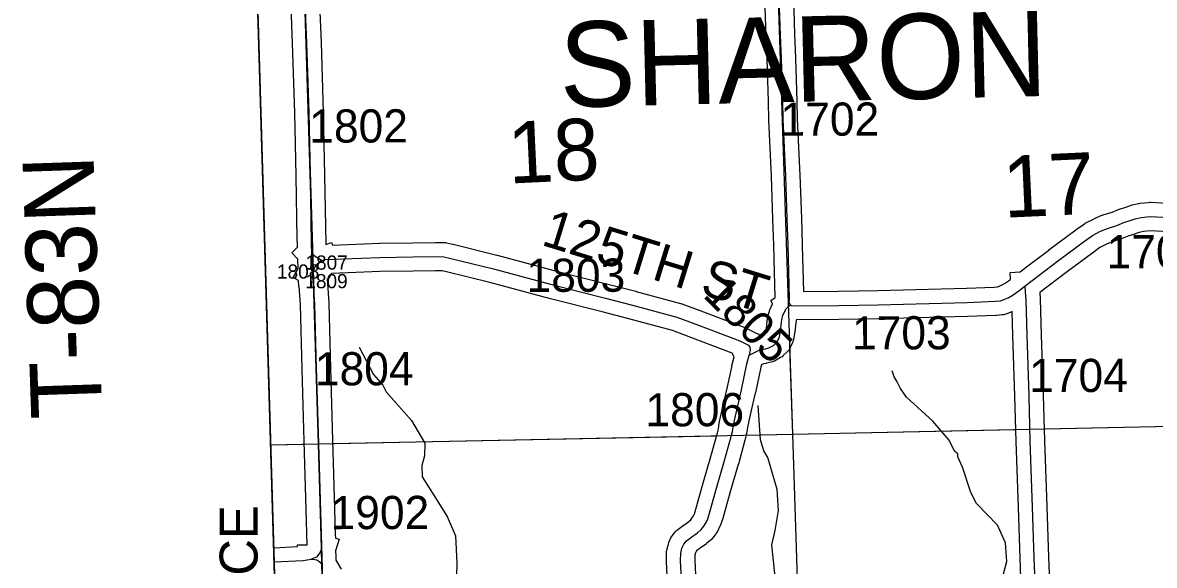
# Model space of a CAD drawing. Extents: x 128.7 to 185.5, y -21.4 to 12.6.
# Drawn here: x 133.254 to 135.642, y 1.081 to 2.226 of the extents above; entities that cross this region are included whole.
import ezdxf

# ---------------------------------------------------------------- set-up
doc = ezdxf.new("R2010")
doc.units = 0
for name, color, linetype in [('tdCoClipBndry', 7, 'Continuous'), ('tdCoCoBndry', 7, 'Continuous'), ('tdCoHydroRiver', 7, 'Continuous'), ('tdCoPipeTxt', 7, 'Continuous'), ('tdCoSecRdNmbr', 7, 'Continuous'), ('tdCoSecRdTxt', 7, 'Continuous'), ('tdCoSecRteBand', 7, 'Continuous'), ('tdCoSecRteCL', 7, 'Continuous'), ('tdCoSectLine', 7, 'Continuous'), ('tdCoSectLinePart', 7, 'Continuous'), ('tdCoSectNmbr', 7, 'Continuous'), ('tdCoSurfGravel', 7, 'Continuous'), ('tdCoTwpBndryShd', 7, 'Continuous'), ('tdCoTwpNameTxt', 7, 'Continuous'), ('tdCoTwpRngTxt', 7, 'Continuous')]:
    doc.layers.add(name, color=color, linetype=linetype)

msp = doc.modelspace()

# ---------------------------------------------------------------- linework, layer by layer
at = {"layer": 'tdCoClipBndry'}
msp.add_lwpolyline([(134.0612, -7.7025), (133.8962, -2.6807), (133.6887, 4.3446), (133.6938, 4.3792), (133.7053, 4.4028), (133.7226, 4.4226), (133.7445, 4.4372), (133.7868, 4.4475), (134.771, 4.4649), (135.7559, 4.4935), (136.7866, 4.5129), (139.7725, 4.5879), (146.7594, 4.806), (147.7608, 4.8492), (149.7557, 4.9088), (150.75, 4.946), (153.7332, 5.0633)], dxfattribs=at)
at = {"layer": 'tdCoCoBndry'}
for p, q in [((133.8784, 1.3376), (133.8476, 2.341)), ((133.8476, 2.341), (133.8784, 1.3376)), ((133.9071, 0.3357), (133.8784, 1.3376)), ((133.8784, 1.3376), (133.9071, 0.3357))]:
    msp.add_line(p, q, dxfattribs=at)
msp.add_lwpolyline([(133.7861, 4.4473), (133.7445, 4.4372), (133.7226, 4.4226), (133.7053, 4.4028), (133.6938, 4.3792), (133.6887, 4.3446), (133.8665, -1.6741), (133.9676, -1.6731), (133.9395, -0.6703), (133.9071, 0.3357), (133.8784, 1.3376), (133.8476, 2.341), (133.8192, 3.3421), (133.789, 4.3475), (133.7889, 4.3556)], close=True, dxfattribs=at)
for points in [[(134.1615, -7.6994), (134.1297, -6.7029), (134.1294, -6.6932), (134.095, -5.6895), (134.0611, -4.6883), (134.0307, -3.6816), (133.9965, -2.6778), (133.9676, -1.6731), (133.9395, -0.6703), (133.9071, 0.3357), (133.8784, 1.3376), (133.8476, 2.341), (133.8192, 3.3421), (133.789, 4.3475), (134.7737, 4.365), (135.7592, 4.3936), (135.7859, 4.3937), (136.7735, 4.4131), (136.7891, 4.4129), (137.7728, 4.4375)], [(133.7886, 4.3475), (133.8188, 3.3421), (133.8473, 2.341), (133.878, 1.3376), (133.9067, 0.3357), (133.9391, -0.6703), (133.9673, -1.6731), (133.9961, -2.6778), (134.0303, -3.6816), (134.0608, -4.6883), (134.0947, -5.6895), (134.129, -6.6932), (134.1293, -6.7029), (134.1612, -7.6994), (134.1875, -8.683), (134.2186, -9.7062), (134.2417, -10.7094), (134.275, -11.7191), (134.2997, -12.7212), (134.329, -13.723)]]:
    msp.add_lwpolyline(points, dxfattribs=at)
at = {"layer": 'tdCoHydroRiver'}
for points in [[(133.9644, 1.5416), (133.9945, 1.4841), (134.0141, 1.461), (134.0209, 1.447), (134.0747, 1.3871), (134.103, 1.339), (134.1022, 1.3122), (134.0965, 1.2915), (134.0972, 1.2679), (134.1237, 1.226), (134.1502, 1.1842), (134.1671, 1.1437), (134.1705, 1.0854), (134.1681, 1.0049)], [(135.3192, 1.0476), (135.3305, 1.089), (135.3277, 1.1283), (135.3107, 1.1657), (135.2667, 1.2116), (135.2549, 1.2349), (135.2375, 1.288), (135.2273, 1.3098), (135.2271, 1.3161), (135.2206, 1.3222), (135.2089, 1.3455), (135.1745, 1.3855), (135.1193, 1.4358), (135.1061, 1.4543), (135.0993, 1.4683), (135.0927, 1.4792), (135.0891, 1.4917)], [(134.8441, 1.0361), (134.8352, 1.1242), (134.8422, 1.1543), (134.8488, 1.1971), (134.8459, 1.2412), (134.8265, 1.3085), (134.8182, 1.3225), (134.8112, 1.3459), (134.8059, 1.4183)]]:
    msp.add_lwpolyline(points, dxfattribs=at)
at = {"layer": 'tdCoSecRteBand'}
for points in [[(133.784, 1.1183), (133.8341, 1.1209), (133.8342, 1.1247), (133.8542, 1.1241), (133.8524, 1.1988), (133.8482, 1.3435), (133.8482, 1.3435), (133.8482, 1.3435), (133.844, 1.4949), (133.844, 1.4949), (133.844, 1.4949), (133.8403, 1.6316), (133.8375, 1.6695), (133.8367, 1.6695), (133.8363, 1.6822), (133.8251, 1.6883), (133.8355, 1.7075), (133.8349, 1.7276), (133.8221, 1.7406), (133.8341, 1.7524), (133.8339, 1.7589), (133.8339, 1.7591), (133.8339, 1.7591), (133.8336, 1.7692), (133.8337, 1.7692), (133.8312, 1.9033), (133.8284, 2.036), (133.8238, 2.1824), (133.819, 2.3006)], [(133.8785, 2.3156), (133.8837, 2.1847), (133.8837, 2.1846), (133.8837, 2.1845), (133.8884, 2.0377), (133.8884, 2.0376), (133.8884, 2.0374), (133.8911, 1.9045), (133.8911, 1.9045), (133.8911, 1.9044), (133.8939, 1.7606), (133.8939, 1.7585), (133.906, 1.7622), (133.9076, 1.757), (134.0068, 1.7609), (134.0072, 1.761), (134.0076, 1.761), (134.0771, 1.762), (134.1252, 1.7627), (134.1259, 1.7627), (134.1265, 1.7627), (134.1435, 1.7622), (134.1461, 1.7621), (134.1486, 1.7616), (134.1609, 1.7592), (134.1615, 1.759), (134.1622, 1.7589), (134.2549, 1.7359), (134.2552, 1.7359), (134.2556, 1.7358), (134.383, 1.7013), (134.4915, 1.674), (134.4916, 1.674), (134.4917, 1.674), (134.5482, 1.6594), (134.5484, 1.6594), (134.5485, 1.6593), (134.6423, 1.6339), (134.6436, 1.6335), (134.645, 1.633), (134.6849, 1.618), (134.6849, 1.618), (134.685, 1.618), (134.7782, 1.5827), (134.7795, 1.5822), (134.7807, 1.5816), (134.7989, 1.5727), (134.8065, 1.5691), (134.8086, 1.5657)], [(134.8086, 1.5657), (134.8096, 1.5659), (134.8173, 1.568), (134.8199, 1.5695), (134.8219, 1.5714), (134.822, 1.5718), (134.8235, 1.5801), (134.8258, 1.6029), (134.8262, 1.6061), (134.8271, 1.6091), (134.8298, 1.6175), (134.8303, 1.6188), (134.8308, 1.62), (134.8365, 1.6333), (134.8366, 1.6337), (134.8326, 1.6399), (134.842, 1.6461), (134.8397, 1.7283), (134.8397, 1.7285), (134.8397, 1.7287), (134.8392, 1.7565), (134.8372, 1.812), (134.8372, 1.812), (134.8372, 1.812), (134.8342, 1.9021), (134.8286, 2.0205), (134.8286, 2.0209), (134.8286, 2.0213), (134.8278, 2.0594), (134.8251, 2.1497), (134.8229, 2.1986), (134.8229, 2.1988), (134.8229, 2.199), (134.8204, 2.2768)], [(134.8804, 2.2791), (134.8829, 2.2011), (134.8851, 2.1522), (134.8851, 2.152), (134.8851, 2.1518), (134.8878, 2.061), (134.8878, 2.0609), (134.8878, 2.0607), (134.8885, 2.0229), (134.8942, 1.9047), (134.8942, 1.9045), (134.8942, 1.9043), (134.8972, 1.814), (134.8991, 1.7584), (134.8991, 1.7581), (134.8992, 1.7578), (134.8996, 1.7299), (134.9017, 1.659)], [(134.9017, 1.659), (134.9756, 1.6598), (135.0584, 1.661), (135.2459, 1.6659), (135.3042, 1.6684), (135.3109, 1.6689), (135.3157, 1.6708), (135.3207, 1.6728), (135.3258, 1.6756), (135.3381, 1.6845), (135.3388, 1.685), (135.338, 1.699), (135.3587, 1.7003), (135.3753, 1.7129), (135.4194, 1.7466), (135.4195, 1.7467), (135.4196, 1.7468), (135.4763, 1.7892), (135.4767, 1.7895), (135.4771, 1.7898), (135.4944, 1.8018), (135.496, 1.803), (135.4977, 1.8039), (135.5147, 1.8127), (135.5159, 1.8134), (135.5171, 1.8139), (135.5314, 1.8198), (135.5326, 1.8203), (135.5337, 1.8206), (135.5527, 1.8267), (135.5665, 1.8322), (135.5674, 1.8326), (135.5683, 1.8329), (135.5815, 1.8372), (135.5915, 1.8408), (135.5934, 1.8415), (135.5954, 1.8419), (135.6082, 1.8446), (135.6097, 1.8449), (135.6112, 1.8451), (135.6297, 1.847), (135.6321, 1.8473), (135.6345, 1.8472), (135.7262, 1.8422)], [(135.7229, 1.7823), (135.6337, 1.7871), (135.6191, 1.7856), (135.6098, 1.7836), (135.6013, 1.7806), (135.6009, 1.7804), (135.6006, 1.7803), (135.5879, 1.7762), (135.574, 1.7706), (135.573, 1.7702), (135.572, 1.7699), (135.5532, 1.7639), (135.5413, 1.7589), (135.5272, 1.7516), (135.5119, 1.7409), (135.4557, 1.6988), (135.4005, 1.6567), (135.4012, 1.6435), (135.4012, 1.6433), (135.4012, 1.643), (135.4034, 1.5678), (135.4076, 1.4399), (135.4076, 1.4398), (135.4076, 1.4397), (135.41, 1.3449), (135.4152, 1.2052), (135.4152, 1.2052), (135.4152, 1.2051), (135.4187, 1.0982), (135.4234, 0.9735)], [(134.617, 0.9966), (134.6126, 1.0899), (134.6125, 1.0908), (134.6125, 1.0918), (134.6128, 1.107), (134.6128, 1.1102), (134.6136, 1.1134), (134.616, 1.124), (134.6166, 1.1265), (134.6177, 1.129), (134.6214, 1.1376), (134.623, 1.1413), (134.6255, 1.1444), (134.6311, 1.1516), (134.6335, 1.1545), (134.6365, 1.1568), (134.6478, 1.1655), (134.6483, 1.1659), (134.6489, 1.1662), (134.6598, 1.1738), (134.6638, 1.1772), (134.6664, 1.1806), (134.6695, 1.1856), (134.6715, 1.1899), (134.6747, 1.1998), (134.6894, 1.2522), (134.6894, 1.2524), (134.6894, 1.2526), (134.7064, 1.3108), (134.7201, 1.3605), (134.7223, 1.3695), (134.7241, 1.382), (134.7243, 1.3835), (134.7246, 1.385), (134.7283, 1.3998), (134.7415, 1.458), (134.751, 1.5028), (134.7506, 1.5029), (134.7531, 1.513), (134.7531, 1.513), (134.7532, 1.5135), (134.7551, 1.5211), (134.7511, 1.5288), (134.6638, 1.5618), (134.6252, 1.5764), (134.533, 1.6014), (134.4768, 1.6158), (134.3681, 1.6432), (134.3679, 1.6433), (134.3676, 1.6433), (134.2402, 1.6778), (134.1485, 1.7005), (134.1393, 1.7023), (134.1255, 1.7027), (134.078, 1.702), (134.078, 1.702), (134.078, 1.702), (134.0088, 1.701), (133.9056, 1.6968), (133.8991, 1.6843), (133.8964, 1.6856), (133.9002, 1.6353), (133.9002, 1.6346), (133.9003, 1.6339), (133.904, 1.4966), (133.9082, 1.3452), (133.9123, 1.2004), (133.9123, 1.2004), (133.9124, 1.2003), (133.9137, 1.1467), (133.9139, 1.1384), (133.9218, 1.1361), (133.9145, 1.1119), (133.9148, 1.1007), (133.915, 1.0917), (133.9265, 1.0729)], [(135.3634, 0.9714), (135.3587, 1.096), (135.3587, 1.0961), (135.3587, 1.0961), (135.3553, 1.2031), (135.3501, 1.3429), (135.3501, 1.343), (135.3501, 1.3432), (135.3476, 1.438), (135.3434, 1.5659), (135.3434, 1.566), (135.3434, 1.566), (135.3419, 1.6166), (135.3376, 1.6149), (135.3375, 1.6149), (135.3375, 1.6149), (135.3286, 1.6115), (135.3246, 1.6099), (135.3203, 1.6095), (135.3087, 1.6085), (135.308, 1.6085), (135.3074, 1.6085), (135.2482, 1.606), (135.248, 1.606), (135.2477, 1.606), (135.0598, 1.601), (135.0597, 1.601), (135.0595, 1.601), (134.9764, 1.5998), (134.9763, 1.5998), (134.9762, 1.5998), (134.887, 1.5989), (134.8865, 1.5977), (134.8852, 1.5936), (134.8831, 1.5729), (134.8829, 1.5719), (134.8828, 1.5708), (134.8806, 1.558), (134.8799, 1.5545), (134.8785, 1.5512), (134.8746, 1.5421), (134.8722, 1.5366), (134.868, 1.5325), (134.8591, 1.5239), (134.8564, 1.5213), (134.8532, 1.5194), (134.8438, 1.514), (134.8403, 1.5119), (134.8363, 1.5109), (134.824, 1.5077), (134.8234, 1.5075), (134.8227, 1.5074), (134.8174, 1.5063), (134.8128, 1.5043), (134.8116, 1.4996), (134.8001, 1.4454), (134.8001, 1.4451), (134.8, 1.4449), (134.7867, 1.3862), (134.7867, 1.386), (134.7866, 1.3857), (134.7833, 1.3722), (134.7815, 1.3596), (134.7813, 1.358), (134.7809, 1.3565), (134.7782, 1.3456), (134.7781, 1.3453), (134.778, 1.345), (134.7642, 1.2947), (134.7641, 1.2945), (134.7641, 1.2942), (134.7471, 1.2359), (134.7324, 1.1831), (134.7322, 1.1825), (134.732, 1.1818), (134.728, 1.1698), (134.7275, 1.1682), (134.7269, 1.1667), (134.7234, 1.1591), (134.7226, 1.1572), (134.7215, 1.1555), (134.7166, 1.1476), (134.7158, 1.1465), (134.715, 1.1454), (134.7096, 1.1382), (134.7076, 1.1356), (134.705, 1.1334), (134.6973, 1.127), (134.6963, 1.1261), (134.6952, 1.1253), (134.6836, 1.1173), (134.6758, 1.1114), (134.675, 1.1103), (134.6739, 1.1078), (134.6727, 1.1029), (134.6726, 1.0917), (134.6769, 0.9992)]]:
    msp.add_lwpolyline(points, dxfattribs=at)
at = {"layer": 'tdCoSecRteCL'}
for p, q in [((133.8657, 1.7004), (133.8645, 1.7402)), ((133.8853, 1.0829), (133.8844, 1.116))]:
    msp.add_line(p, q, dxfattribs=at)
for points in [[(134.874, 1.6311), (134.8714, 1.6352), (134.8721, 1.6436), (134.8697, 1.7292), (134.8692, 1.7573), (134.8672, 1.813), (134.8642, 1.9033), (134.8586, 2.0219), (134.8578, 2.0601), (134.8551, 2.1509), (134.8529, 2.1999), (134.8504, 2.2781), (134.846, 2.361), (134.845, 2.3916), (134.8435, 2.4187), (134.8445, 2.4404), (134.8443, 2.4796), (134.843, 2.4939), (134.8425, 2.521), (134.8403, 2.5817), (134.8396, 2.6091)], [(133.8645, 1.7402), (133.8639, 1.7599), (133.8612, 1.9039), (133.8584, 2.0368), (133.8538, 2.1835), (133.8483, 2.3182), (133.8479, 2.3315)], [(135.3697, 1.6709), (135.4376, 1.7228), (135.4943, 1.7652), (135.5116, 1.7773), (135.5286, 1.7861), (135.5429, 1.7921), (135.5629, 1.7985), (135.5777, 1.8044), (135.5912, 1.8088), (135.6016, 1.8125), (135.6144, 1.8152), (135.6329, 1.8172), (135.7246, 1.8123), (135.84, 1.8054), (135.8644, 1.8036)], [(133.8645, 1.7402), (133.8687, 1.7359), (133.8739, 1.7312), (133.8788, 1.7285), (133.8862, 1.7247)], [(133.8657, 1.7004), (133.8707, 1.7095), (133.8768, 1.7179), (133.8842, 1.7241), (133.8862, 1.7247)], [(133.8862, 1.7247), (133.8914, 1.7263), (134.008, 1.731), (134.0776, 1.732), (134.1257, 1.7327), (134.1427, 1.7322), (134.155, 1.7297), (134.2477, 1.7068), (134.3755, 1.6723), (134.4842, 1.6449), (134.5407, 1.6304), (134.6344, 1.605), (134.6744, 1.5899), (134.7676, 1.5546), (134.7858, 1.5458), (134.7885, 1.5416), (134.789, 1.5354), (134.7878, 1.5283), (134.787, 1.5249)], [(133.8844, 1.116), (133.8824, 1.1996), (133.8782, 1.3443), (133.874, 1.4957), (133.8703, 1.6331), (133.8661, 1.6891), (133.8657, 1.7004)], [(134.874, 1.6311), (134.8741, 1.631), (134.8763, 1.6293), (134.8798, 1.6288), (134.9759, 1.6298), (135.059, 1.631), (135.247, 1.636), (135.3061, 1.6384), (135.3177, 1.6394), (135.3266, 1.6429), (135.3335, 1.6456), (135.3419, 1.6503), (135.356, 1.6604), (135.3697, 1.6709)], [(135.4336, -0.1372), (135.4306, -0.1273), (135.4291, -0.0834), (135.4254, 0.0049), (135.4203, 0.1356), (135.4166, 0.2466), (135.4138, 0.3366), (135.4114, 0.4078), (135.4079, 0.5255), (135.4037, 0.6244), (135.4, 0.7329), (135.3966, 0.848), (135.3934, 0.9723), (135.3887, 1.0971), (135.3852, 1.2041), (135.3801, 1.344), (135.3776, 1.4389), (135.3734, 1.5669), (135.3712, 1.6421), (135.3704, 1.6576), (135.3697, 1.6709)], [(134.787, 1.5249), (134.798, 1.5306), (134.8083, 1.535), (134.8165, 1.5367), (134.8288, 1.5399), (134.8382, 1.5454), (134.847, 1.554), (134.851, 1.5631), (134.8532, 1.576), (134.8557, 1.5999), (134.8584, 1.6083), (134.8641, 1.6216), (134.874, 1.6311)], [(134.647, 0.9978), (134.6425, 1.0913), (134.6428, 1.1066), (134.6453, 1.1172), (134.649, 1.1258), (134.6546, 1.133), (134.666, 1.1416), (134.6781, 1.15), (134.6857, 1.1564), (134.6911, 1.1635), (134.6961, 1.1714), (134.6995, 1.1791), (134.7035, 1.1912), (134.7183, 1.2442), (134.7353, 1.3026), (134.7491, 1.3529), (134.7518, 1.3638), (134.7538, 1.3778), (134.7575, 1.3929), (134.7708, 1.4516), (134.7824, 1.5063), (134.787, 1.5249)], [(133.8844, 1.116), (133.8826, 1.11), (133.8792, 1.1044), (133.874, 1.0984), (133.8632, 1.0938)], [(133.7849, 1.0883), (133.8461, 1.0915), (133.8632, 1.0938)], [(133.8632, 1.0938), (133.8706, 1.0935), (133.8752, 1.0925), (133.8794, 1.0901), (133.8831, 1.0864), (133.8853, 1.0829)], [(133.9483, -0.9759), (133.9454, -0.8856), (133.9431, -0.8057), (133.9412, -0.7369), (133.9382, -0.6198), (133.9352, -0.5123), (133.9315, -0.3922), (133.9283, -0.2565), (133.9252, -0.1552), (133.9252, -0.1551), (133.9208, -0.0589), (133.9157, 0.0817), (133.9107, 0.2208), (133.9063, 0.3576), (133.9009, 0.511), (133.8977, 0.6477), (133.894, 0.7752), (133.8893, 0.9241), (133.8858, 1.0602), (133.8853, 1.0829)]]:
    msp.add_lwpolyline(points, dxfattribs=at)
at = {"layer": 'tdCoSectLine'}
for points in [[(133.8473, 2.341), (133.878, 1.3376)], [(134.8456, 2.361), (134.8785, 1.3578)], [(134.8785, 1.3578), (135.8778, 1.379)], [(133.7776, 1.3356), (133.878, 1.3376)], [(133.878, 1.3376), (134.8785, 1.3578)], [(133.878, 1.3376), (133.9067, 0.3357)], [(134.8785, 1.3578), (134.9111, 0.3555)]]:
    msp.add_lwpolyline(points, dxfattribs=at)
at = {"layer": 'tdCoSectLinePart'}
for points in [[(134.8725, 1.5401), (134.8785, 1.3578)], [(134.8785, 1.3578), (135.349, 1.3678)], [(135.4095, 1.3691), (135.8472, 1.3783)], [(133.9079, 1.3382), (134.718, 1.3546)], [(134.78, 1.3559), (134.8785, 1.3578)], [(134.8785, 1.3578), (134.9111, 0.3555)], [(133.7776, 1.3356), (133.848, 1.337)]]:
    msp.add_lwpolyline(points, dxfattribs=at)
at = {"layer": 'tdCoSurfGravel'}
msp.add_line((133.8657, 1.7004), (133.8645, 1.7402), dxfattribs=at)
for points in [[(133.8645, 1.7402), (133.8639, 1.7599), (133.8612, 1.9039), (133.8584, 2.0368), (133.8538, 2.1835), (133.8483, 2.3182), (133.8479, 2.3315), (133.8471, 2.3601), (133.8439, 2.4656), (133.8402, 2.569), (133.8375, 2.71), (133.835, 2.8289), (133.8346, 2.8416), (133.8313, 2.9441), (133.8303, 2.9899), (133.8254, 3.1421), (133.8212, 3.2886), (133.8192, 3.3421), (133.8165, 3.4129), (133.8128, 3.5431), (133.8104, 3.6678), (133.8059, 3.8037), (133.8064, 3.8304)], [(134.874, 1.6311), (134.8714, 1.6352), (134.8721, 1.6436), (134.8697, 1.7292), (134.8692, 1.7573), (134.8672, 1.813), (134.8642, 1.9033), (134.8586, 2.0219), (134.8578, 2.0601), (134.8551, 2.1509), (134.8529, 2.1999), (134.8504, 2.2781)], [(133.8862, 1.7247), (133.8914, 1.7263), (134.008, 1.731), (134.0776, 1.732), (134.1257, 1.7327), (134.1427, 1.7322), (134.155, 1.7297), (134.2477, 1.7068), (134.3755, 1.6723), (134.4842, 1.6449), (134.5407, 1.6304), (134.6344, 1.605), (134.6744, 1.5899), (134.7676, 1.5546), (134.7858, 1.5458), (134.7885, 1.5416), (134.789, 1.5354), (134.7878, 1.5283), (134.787, 1.5249), (134.798, 1.5306), (134.8083, 1.535), (134.8165, 1.5367), (134.8288, 1.5399), (134.8382, 1.5454), (134.847, 1.554), (134.851, 1.5631), (134.8532, 1.576), (134.8557, 1.5999), (134.8584, 1.6083), (134.8641, 1.6216), (134.874, 1.6311), (134.8741, 1.631), (134.8763, 1.6293), (134.8798, 1.6288), (134.9759, 1.6298), (135.059, 1.631), (135.247, 1.636), (135.3061, 1.6384), (135.3177, 1.6394), (135.3266, 1.6429), (135.3335, 1.6456), (135.3419, 1.6503), (135.356, 1.6604), (135.3697, 1.6709), (135.4376, 1.7228), (135.4943, 1.7652), (135.5116, 1.7773), (135.5286, 1.7861), (135.5429, 1.7921), (135.5629, 1.7985), (135.5777, 1.8044), (135.5912, 1.8088), (135.6016, 1.8125), (135.6144, 1.8152), (135.6329, 1.8172), (135.7246, 1.8123)], [(133.8645, 1.7402), (133.8687, 1.7359), (133.8739, 1.7312), (133.8788, 1.7285), (133.8862, 1.7247)], [(133.8657, 1.7004), (133.8707, 1.7095), (133.8768, 1.7179), (133.8842, 1.7241), (133.8862, 1.7247)], [(133.9252, -0.1551), (133.9208, -0.0589), (133.9157, 0.0817), (133.9107, 0.2208), (133.9063, 0.3576), (133.9009, 0.511), (133.8977, 0.6477), (133.894, 0.7752), (133.8893, 0.9241), (133.8858, 1.0602), (133.8853, 1.0829), (133.8844, 1.116), (133.8824, 1.1996), (133.8782, 1.3443), (133.874, 1.4957), (133.8703, 1.6331), (133.8661, 1.6891), (133.8657, 1.7004)], [(135.4114, 0.4078), (135.4079, 0.5255), (135.4037, 0.6244), (135.4, 0.7329), (135.3966, 0.848), (135.3934, 0.9723), (135.3887, 1.0971), (135.3852, 1.2041), (135.3801, 1.344), (135.3776, 1.4389), (135.3734, 1.5669), (135.3712, 1.6421), (135.3704, 1.6576), (135.3697, 1.6709)], [(134.647, 0.9978), (134.6425, 1.0913), (134.6428, 1.1066), (134.6453, 1.1172), (134.649, 1.1258), (134.6546, 1.133), (134.666, 1.1416), (134.6781, 1.15), (134.6857, 1.1564), (134.6911, 1.1635), (134.6961, 1.1714), (134.6995, 1.1791), (134.7035, 1.1912), (134.7183, 1.2442), (134.7353, 1.3026), (134.7491, 1.3529), (134.7518, 1.3638), (134.7538, 1.3778), (134.7575, 1.3929), (134.7708, 1.4516), (134.7824, 1.5063), (134.787, 1.5249)], [(133.8844, 1.116), (133.8826, 1.11), (133.8792, 1.1044), (133.874, 1.0984), (133.8632, 1.0938)], [(133.7849, 1.0883), (133.8461, 1.0915), (133.8632, 1.0938), (133.8706, 1.0935), (133.8752, 1.0925), (133.8794, 1.0901), (133.8831, 1.0864), (133.8853, 1.0829)]]:
    msp.add_lwpolyline(points, dxfattribs=at)
at = {"layer": 'tdCoTwpBndryShd'}
msp.add_lwpolyline([(133.7886, 4.3475), (133.8188, 3.3421), (133.8473, 2.341), (133.878, 1.3376), (133.9067, 0.3357), (133.9391, -0.6703), (133.9673, -1.6731), (133.9961, -2.6778), (134.0303, -3.6816), (134.0608, -4.6883), (134.0947, -5.6895), (134.129, -6.6932), (134.1293, -6.7029), (134.1612, -7.6994)], dxfattribs=at)

# ---------------------------------------------------------------- texts
at = {"layer": 'tdCoPipeTxt'}
msp.add_text('ALLIANCE', height=0.08, rotation=90, dxfattribs=at).set_placement((133.7498, 0.6906))
at = {"layer": 'tdCoSecRdNmbr'}
for s, height, rotation, p in [('1702', 0.07, 0.1031, (134.8533, 1.9876)), ('1802', 0.07, 0.1024, (133.8589, 1.9732)), ('1705', 0.07, 0.1037, (135.5413, 1.7081)), ('1807', 0.03, 0.108, (133.8509, 1.705)), ('1803', 0.07, 0.1027, (134.3174, 1.6582)), ('1808', 0.03, 0.108, (133.7908, 1.6861)), ('1809', 0.03, 0.108, (133.8507, 1.6658)), ('1805', 0.07, 315.1025, (134.6876, 1.6493)), ('1703', 0.07, 0.1032, (135.0041, 1.5367)), ('1804', 0.07, 0.1024, (133.8708, 1.4608)), ('1704', 0.07, 0.1035, (135.3778, 1.4467)), ('1806', 0.07, 0.1029, (134.5682, 1.3744)), ('1902', 0.07, 0.1024, (133.9039, 1.1574))]:
    msp.add_text(s, height=height, rotation=rotation, dxfattribs=at).set_placement(p)
at = {"layer": 'tdCoSecRdTxt'}
msp.add_text('125TH ST', height=0.08, rotation=342.7772, dxfattribs=at).set_placement((134.346, 1.758))
at = {"layer": 'tdCoSectNmbr'}
for s, rotation, p in [('18', 2.655, (134.2803, 1.8868)), ('17', 2.6558, (135.325, 1.8146))]:
    msp.add_text(s, height=0.13, rotation=rotation, dxfattribs=at).set_placement(p)
at = {"layer": 'tdCoTwpNameTxt'}
msp.add_text('SHARON', height=0.18, rotation=1.3539, dxfattribs=at).set_placement((134.3885, 2.0475))
at = {"layer": 'tdCoTwpRngTxt'}
msp.add_text('T-83N', height=0.15, rotation=91.9399, dxfattribs=at).set_placement((133.4223, 1.3929))

doc.saveas('drawing.dxf')
